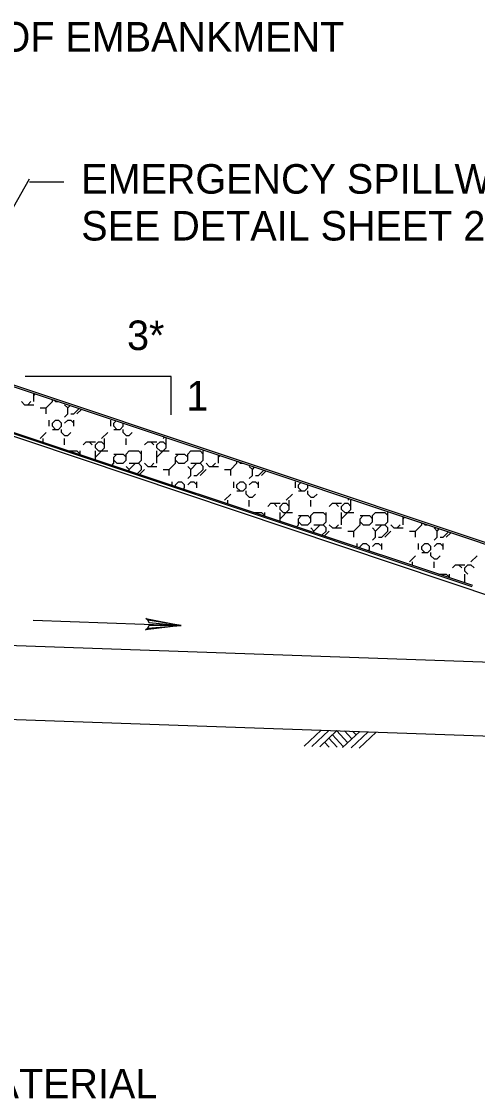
# Model space of a CAD drawing. Extents: x 636462 to 639890, y 299944 to 300538.
# Drawn here: x 638498.9 to 638545.1, y 300084.3 to 300193.5 of the extents above; entities that cross this region are included whole.
import ezdxf

# ---------------------------------------------------------------- set-up
doc = ezdxf.new("R2010")
doc.units = 0
doc.layers.add('Default', color=7, linetype='Continuous')

msp = doc.modelspace()

# ---------------------------------------------------------------- linework, layer by layer
at = {"layer": 'Default'}
for p, q in [((638489.42, 300159.53), (638499.66, 300177.55)), ((638503.16, 300177.22), (638499.66, 300177.22)), ((638465.99, 300167.34), (638586.56, 300127.15)), ((638500.1, 300154.96), (638500.1, 300155.8)), ((638499.16, 300154.65), (638498.85, 300154.96)), ((638499.48, 300154.65), (638499.79, 300154.96)), ((638500.1, 300155.58), (638500.26, 300155.75)), ((638501.35, 300154.33), (638501.98, 300154.96)), ((638501.98, 300154.96), (638501.98, 300155.17)), ((638502.29, 300154.96), (638502.12, 300155.12)), ((638502.29, 300154.96), (638502.61, 300154.96)), ((638499.16, 300154.65), (638500.1, 300154.65)), ((638500.73, 300154.33), (638501.35, 300154.33)), ((638501.35, 300153.71), (638501.35, 300154.33)), ((638503.54, 300154.33), (638503.22, 300154.65)), ((638503.22, 300153.4), (638503.54, 300153.71)), ((638503.54, 300154.33), (638503.77, 300154.57)), ((638503.54, 300153.71), (638503.54, 300154.33)), ((638503.85, 300153.71), (638504.16, 300153.71)), ((638504.16, 300153.71), (638504.71, 300154.26)), ((638504.47, 300153.71), (638504.94, 300154.18)), ((638501.66, 300152.46), (638501.66, 300153.09)), ((638501.98, 300152.77), (638502.29, 300153.09)), ((638501.98, 300152.46), (638501.98, 300152.77)), ((638502.29, 300153.09), (638502.6, 300153.09)), ((638502.91, 300152.77), (638502.6, 300153.09)), ((638502.91, 300152.46), (638502.91, 300152.77)), ((638503.22, 300152.77), (638503.54, 300153.09)), ((638503.54, 300153.09), (638503.85, 300153.09)), ((638504.16, 300152.77), (638503.85, 300153.09)), ((638504.16, 300152.46), (638504.16, 300153.09)), ((638507.91, 300152.46), (638507.91, 300153.09)), ((638508.22, 300152.77), (638508.46, 300153.01)), ((638508.22, 300152.46), (638508.22, 300152.77)), ((638509.16, 300152.77), (638509.16, 300152.77)), ((638509.16, 300152.46), (638509.16, 300152.77)), ((638500.73, 300151.21), (638501.35, 300151.84)), ((638502.29, 300152.15), (638501.98, 300152.46)), ((638501.98, 300152.15), (638502.6, 300152.15)), ((638502.6, 300152.15), (638502.91, 300152.46)), ((638502.91, 300151.84), (638502.91, 300152.15)), ((638503.22, 300151.52), (638502.91, 300151.84)), ((638503.22, 300151.52), (638503.54, 300151.52)), ((638503.54, 300151.52), (638503.85, 300151.84)), ((638506.97, 300151.21), (638507.6, 300151.84)), ((638508.53, 300152.15), (638508.22, 300152.46)), ((638508.22, 300152.15), (638508.85, 300152.15)), ((638508.85, 300152.15), (638509.16, 300152.46)), ((638509.16, 300151.84), (638509.16, 300152.15)), ((638509.47, 300151.52), (638509.16, 300151.84)), ((638509.47, 300151.52), (638509.78, 300151.52)), ((638509.78, 300151.52), (638510.09, 300151.84)), ((638501.04, 300150.8), (638501.04, 300151.21)), ((638503.22, 300150.59), (638503.22, 300151.21)), ((638505.1, 300150.59), (638505.41, 300150.9)), ((638505.41, 300150.9), (638506.35, 300150.9)), ((638506.03, 300150.59), (638505.72, 300150.9)), ((638506.35, 300150.59), (638506.66, 300150.9)), ((638506.35, 300150.28), (638506.35, 300150.59)), ((638506.66, 300150.9), (638506.97, 300150.9)), ((638507.28, 300150.59), (638506.97, 300150.9)), ((638507.28, 300150.28), (638507.28, 300151.21)), ((638509.47, 300150.59), (638509.47, 300151.21)), ((638511.34, 300150.59), (638511.66, 300150.9)), ((638511.66, 300150.9), (638512.59, 300150.9)), ((638512.28, 300150.59), (638511.97, 300150.9)), ((638512.59, 300150.59), (638512.91, 300150.9)), ((638512.59, 300150.28), (638512.59, 300150.59)), ((638512.91, 300150.9), (638513.22, 300150.9)), ((638513.22, 300151.21), (638513.37, 300151.37)), ((638513.53, 300150.59), (638513.22, 300150.9)), ((638513.53, 300150.28), (638513.53, 300151.21)), ((638503.56, 300149.96), (638504.47, 300149.96)), ((638504.79, 300149.65), (638504.47, 300149.96)), ((638504.79, 300149.56), (638504.79, 300149.96)), ((638506.66, 300149.96), (638506.35, 300150.28)), ((638506.35, 300149.34), (638507.28, 300150.28)), ((638506.35, 300149.04), (638506.35, 300149.96)), ((638506.66, 300149.96), (638507.6, 300149.96)), ((638508.22, 300149.34), (638508.53, 300149.65)), ((638508.22, 300149.65), (638509.16, 300149.65)), ((638508.22, 300148.71), (638508.22, 300149.34)), ((638509.47, 300149.34), (638509.16, 300149.65)), ((638509.47, 300149.65), (638509.78, 300149.96)), ((638509.47, 300149.03), (638509.47, 300149.65)), ((638509.78, 300149.96), (638510.72, 300149.96)), ((638511.03, 300149.65), (638510.72, 300149.96)), ((638511.03, 300149.03), (638511.03, 300149.96)), ((638512.91, 300149.96), (638512.59, 300150.28)), ((638512.59, 300149.34), (638513.53, 300150.28)), ((638512.59, 300148.71), (638512.59, 300149.96)), ((638512.91, 300149.96), (638513.84, 300149.96)), ((638514.47, 300149.34), (638514.78, 300149.65)), ((638514.47, 300149.65), (638515.4, 300149.65)), ((638514.47, 300148.71), (638514.47, 300149.34)), ((638515.72, 300149.34), (638515.4, 300149.65)), ((638515.72, 300149.65), (638516.03, 300149.96)), ((638515.72, 300149.03), (638515.72, 300149.65)), ((638516.03, 300149.96), (638516.97, 300149.96)), ((638517.28, 300149.65), (638516.97, 300149.96)), ((638517.28, 300149.03), (638517.28, 300149.96)), ((638518.84, 300148.71), (638518.84, 300149.54)), ((638518.84, 300149.34), (638518.99, 300149.49)), ((638508, 300148.49), (638508.22, 300148.71)), ((638508.53, 300148.71), (638508.22, 300149.03)), ((638508.53, 300148.71), (638509.16, 300148.71)), ((638509.16, 300148.71), (638509.47, 300149.03)), ((638509.78, 300148.09), (638509.47, 300148.4)), ((638509.78, 300148.09), (638510.41, 300148.71)), ((638509.78, 300148.71), (638510.72, 300148.71)), ((638510.72, 300148.71), (638511.03, 300149.03)), ((638511.03, 300148.4), (638510.72, 300148.71)), ((638511.03, 300148.09), (638511.03, 300148.4)), ((638511.66, 300148.4), (638511.34, 300148.71)), ((638511.66, 300148.4), (638512.59, 300148.4)), ((638511.97, 300148.4), (638512.28, 300148.71)), ((638513.84, 300148.09), (638514.47, 300148.71)), ((638514.78, 300148.71), (638514.47, 300149.03)), ((638514.78, 300148.71), (638515.4, 300148.71)), ((638515.4, 300148.71), (638515.72, 300149.03)), ((638516.03, 300148.09), (638515.72, 300148.4)), ((638516.03, 300148.09), (638516.65, 300148.71)), ((638516.03, 300148.71), (638516.97, 300148.71)), ((638516.97, 300148.71), (638517.28, 300149.03)), ((638517.28, 300148.4), (638516.97, 300148.71)), ((638517.28, 300148.09), (638517.28, 300148.4)), ((638517.9, 300148.4), (638517.59, 300148.71)), ((638517.9, 300148.4), (638518.84, 300148.4)), ((638518.21, 300148.4), (638518.53, 300148.71)), ((638520.09, 300148.09), (638520.71, 300148.71)), ((638520.71, 300148.71), (638520.71, 300148.92)), ((638521.03, 300148.71), (638520.88, 300148.86)), ((638521.03, 300148.71), (638521.32, 300148.71)), ((638522.27, 300148.09), (638521.96, 300148.4)), ((638522.27, 300148.09), (638522.5, 300148.32)), ((638509.78, 300147.9), (638509.78, 300148.09)), ((638510.58, 300147.63), (638511.03, 300148.09)), ((638510.81, 300147.56), (638511.34, 300148.09)), ((638513.22, 300148.09), (638513.84, 300148.09)), ((638513.84, 300147.46), (638513.84, 300148.09)), ((638515.72, 300147.15), (638516.03, 300147.46)), ((638516.03, 300147.46), (638516.03, 300148.09)), ((638516.34, 300147.46), (638516.65, 300147.46)), ((638516.65, 300147.46), (638517.28, 300148.09)), ((638516.97, 300147.46), (638517.59, 300148.09)), ((638519.46, 300148.09), (638520.09, 300148.09)), ((638520.09, 300147.46), (638520.09, 300148.09)), ((638521.96, 300147.15), (638522.27, 300147.46)), ((638522.27, 300147.46), (638522.27, 300148.09)), ((638522.59, 300147.46), (638522.9, 300147.46)), ((638522.9, 300147.46), (638523.44, 300148.01)), ((638523.21, 300147.46), (638523.67, 300147.93)), ((638514.15, 300146.45), (638514.15, 300146.84)), ((638514.47, 300146.53), (638514.78, 300146.84)), ((638514.47, 300146.34), (638514.47, 300146.53)), ((638514.78, 300146.84), (638515.09, 300146.84)), ((638515.4, 300146.53), (638515.09, 300146.84)), ((638515.27, 300146.08), (638515.4, 300146.22)), ((638515.4, 300146.22), (638515.4, 300146.53)), ((638515.72, 300146.53), (638516.03, 300146.84)), ((638516.03, 300146.84), (638516.34, 300146.84)), ((638516.65, 300146.53), (638516.34, 300146.84)), ((638516.65, 300146.22), (638516.65, 300146.84)), ((638520.4, 300146.22), (638520.4, 300146.84)), ((638520.71, 300146.53), (638521.03, 300146.84)), ((638520.71, 300146.22), (638520.71, 300146.53)), ((638521.03, 300145.9), (638520.71, 300146.22)), ((638521.03, 300146.84), (638521.34, 300146.84)), ((638521.65, 300146.53), (638521.34, 300146.84)), ((638521.34, 300145.9), (638521.65, 300146.22)), ((638521.65, 300146.22), (638521.65, 300146.53)), ((638521.96, 300146.53), (638522.27, 300146.84)), ((638522.27, 300146.84), (638522.59, 300146.84)), ((638522.9, 300146.53), (638522.59, 300146.84)), ((638522.9, 300146.22), (638522.9, 300146.84)), ((638526.65, 300146.22), (638526.65, 300146.84)), ((638526.96, 300146.53), (638527.19, 300146.75)), ((638526.96, 300146.22), (638526.96, 300146.53)), ((638527.27, 300145.9), (638526.96, 300146.22)), ((638527.58, 300145.9), (638527.9, 300146.22)), ((638527.9, 300146.22), (638527.9, 300146.52)), ((638519.46, 300144.97), (638520.09, 300145.59)), ((638519.78, 300144.58), (638519.78, 300144.97)), ((638520.71, 300145.9), (638521.34, 300145.9)), ((638521.65, 300145.59), (638521.65, 300145.9)), ((638521.96, 300145.28), (638521.65, 300145.59)), ((638521.96, 300145.28), (638522.27, 300145.28)), ((638521.96, 300144.34), (638521.96, 300144.97)), ((638522.27, 300145.28), (638522.59, 300145.59)), ((638525.71, 300144.97), (638526.33, 300145.59)), ((638526.02, 300144.03), (638526.02, 300144.97)), ((638526.96, 300145.9), (638527.58, 300145.9)), ((638527.9, 300145.59), (638527.9, 300145.9)), ((638528.21, 300145.28), (638527.9, 300145.59)), ((638528.21, 300145.28), (638528.52, 300145.28)), ((638528.21, 300144.34), (638528.21, 300144.97)), ((638528.52, 300145.28), (638528.83, 300145.59)), ((638531.96, 300144.97), (638532.1, 300145.11)), ((638532.27, 300144.03), (638532.27, 300144.97)), ((638523.84, 300144.34), (638524.15, 300144.65)), ((638524.15, 300144.65), (638525.09, 300144.65)), ((638524.77, 300144.34), (638524.46, 300144.65)), ((638525.09, 300144.34), (638525.4, 300144.65)), ((638525.09, 300144.03), (638525.09, 300144.34)), ((638525.4, 300143.72), (638525.09, 300144.03)), ((638525.09, 300143.09), (638526.02, 300144.03)), ((638525.4, 300144.65), (638525.71, 300144.65)), ((638526.02, 300144.34), (638525.71, 300144.65)), ((638530.08, 300144.34), (638530.39, 300144.65)), ((638530.39, 300144.65), (638531.33, 300144.65)), ((638531.02, 300144.34), (638530.71, 300144.65)), ((638531.33, 300144.34), (638531.64, 300144.65)), ((638531.33, 300144.03), (638531.33, 300144.34)), ((638531.64, 300143.72), (638531.33, 300144.03)), ((638531.33, 300143.09), (638532.27, 300144.03)), ((638531.64, 300144.65), (638531.96, 300144.65)), ((638532.27, 300144.34), (638531.96, 300144.65)), ((638522.38, 300143.72), (638523.21, 300143.72)), ((638523.52, 300143.4), (638523.21, 300143.72)), ((638523.52, 300143.34), (638523.52, 300143.72)), ((638525.09, 300142.82), (638525.09, 300143.72)), ((638525.4, 300143.72), (638526.33, 300143.72)), ((638526.96, 300143.09), (638527.27, 300143.4)), ((638526.96, 300143.4), (638527.9, 300143.4)), ((638526.96, 300142.47), (638526.96, 300143.09)), ((638527.27, 300142.47), (638526.96, 300142.78)), ((638528.21, 300143.09), (638527.9, 300143.4)), ((638527.9, 300142.47), (638528.21, 300142.78)), ((638528.21, 300143.4), (638528.52, 300143.72)), ((638528.21, 300142.78), (638528.21, 300143.4)), ((638528.52, 300143.72), (638529.46, 300143.72)), ((638529.77, 300143.4), (638529.46, 300143.72)), ((638529.46, 300142.47), (638529.77, 300142.78)), ((638529.77, 300142.78), (638529.77, 300143.72)), ((638531.33, 300142.47), (638531.33, 300143.72)), ((638531.64, 300143.72), (638532.58, 300143.72)), ((638533.2, 300143.09), (638533.52, 300143.4)), ((638533.2, 300143.4), (638534.14, 300143.4)), ((638533.2, 300142.47), (638533.2, 300143.09)), ((638533.52, 300142.47), (638533.2, 300142.78)), ((638534.45, 300143.09), (638534.14, 300143.4)), ((638534.14, 300142.47), (638534.45, 300142.78)), ((638534.45, 300143.4), (638534.77, 300143.72)), ((638534.45, 300142.78), (638534.45, 300143.4)), ((638534.77, 300143.72), (638535.7, 300143.72)), ((638536.02, 300143.4), (638535.7, 300143.72)), ((638535.7, 300142.47), (638536.02, 300142.78)), ((638536.02, 300142.78), (638536.02, 300143.72)), ((638537.58, 300142.47), (638537.58, 300143.28)), ((638537.58, 300143.09), (638537.72, 300143.24)), ((638526.75, 300142.26), (638526.96, 300142.47)), ((638527.27, 300142.47), (638527.9, 300142.47)), ((638528.52, 300141.84), (638528.21, 300142.16)), ((638528.52, 300141.84), (638529.14, 300142.47)), ((638528.52, 300142.47), (638529.46, 300142.47)), ((638528.52, 300141.68), (638528.52, 300141.84)), ((638529.33, 300141.41), (638529.77, 300141.84)), ((638529.77, 300142.16), (638529.46, 300142.47)), ((638529.57, 300141.33), (638530.08, 300141.84)), ((638529.77, 300141.84), (638529.77, 300142.16)), ((638530.39, 300142.16), (638530.08, 300142.47)), ((638530.39, 300142.16), (638531.33, 300142.16)), ((638530.71, 300142.16), (638531.02, 300142.47)), ((638531.96, 300141.84), (638532.58, 300141.84)), ((638532.58, 300141.84), (638533.2, 300142.47)), ((638532.58, 300141.22), (638532.58, 300141.84)), ((638533.52, 300142.47), (638534.14, 300142.47)), ((638534.77, 300141.84), (638534.45, 300142.16)), ((638534.77, 300141.84), (638535.39, 300142.47)), ((638534.77, 300142.47), (638535.7, 300142.47)), ((638534.77, 300141.22), (638534.77, 300141.84)), ((638535.39, 300141.22), (638536.02, 300141.84)), ((638536.02, 300142.16), (638535.7, 300142.47)), ((638535.7, 300141.22), (638536.33, 300141.84)), ((638536.02, 300141.84), (638536.02, 300142.16)), ((638536.64, 300142.16), (638536.33, 300142.47)), ((638536.64, 300142.16), (638537.58, 300142.16)), ((638536.95, 300142.16), (638537.26, 300142.47)), ((638538.2, 300141.84), (638538.83, 300141.84)), ((638538.83, 300141.84), (638539.45, 300142.47)), ((638538.83, 300141.22), (638538.83, 300141.84)), ((638539.45, 300142.47), (638539.45, 300142.66)), ((638539.76, 300142.47), (638539.63, 300142.6)), ((638539.76, 300142.47), (638540.02, 300142.47)), ((638541.01, 300141.84), (638540.7, 300142.16)), ((638541.01, 300141.84), (638541.23, 300142.06)), ((638541.01, 300141.22), (638541.01, 300141.84)), ((638541.64, 300141.22), (638542.17, 300141.75)), ((638541.95, 300141.22), (638542.4, 300141.67)), ((638532.89, 300140.23), (638532.89, 300140.59)), ((638533.2, 300140.28), (638533.52, 300140.59)), ((638533.52, 300140.59), (638533.83, 300140.59)), ((638534.14, 300140.28), (638533.83, 300140.59)), ((638534.45, 300140.91), (638534.77, 300141.22)), ((638534.45, 300140.28), (638534.77, 300140.59)), ((638534.77, 300140.59), (638535.08, 300140.59)), ((638535.08, 300141.22), (638535.39, 300141.22)), ((638535.39, 300140.28), (638535.08, 300140.59)), ((638535.39, 300139.97), (638535.39, 300140.59)), ((638539.14, 300139.97), (638539.14, 300140.59)), ((638539.45, 300140.28), (638539.76, 300140.59)), ((638539.76, 300140.59), (638540.08, 300140.59)), ((638540.39, 300140.28), (638540.08, 300140.59)), ((638540.7, 300140.91), (638541.01, 300141.22)), ((638540.7, 300140.28), (638541.01, 300140.59)), ((638541.01, 300140.59), (638541.32, 300140.59)), ((638541.32, 300141.22), (638541.64, 300141.22)), ((638541.64, 300140.28), (638541.32, 300140.59)), ((638541.64, 300139.97), (638541.64, 300140.59)), ((638533.2, 300140.12), (638533.2, 300140.28)), ((638534.02, 300139.85), (638534.14, 300139.97)), ((638534.14, 300139.97), (638534.14, 300140.28)), ((638539.45, 300139.97), (638539.45, 300140.28)), ((638539.76, 300139.66), (638539.45, 300139.97)), ((638539.45, 300139.66), (638540.08, 300139.66)), ((638540.08, 300139.66), (638540.39, 300139.97)), ((638540.39, 300139.97), (638540.39, 300140.28)), ((638540.39, 300139.34), (638540.39, 300139.66)), ((638538.2, 300138.72), (638538.83, 300139.34)), ((638538.51, 300138.36), (638538.51, 300138.72)), ((638540.7, 300139.03), (638540.39, 300139.34)), ((638540.7, 300139.03), (638541.01, 300139.03)), ((638540.7, 300138.1), (638540.7, 300138.72)), ((638541.01, 300139.03), (638541.32, 300139.34)), ((638542.57, 300138.1), (638542.89, 300138.41)), ((638542.89, 300138.41), (638543.82, 300138.41)), ((638543.51, 300138.1), (638543.2, 300138.41)), ((638543.82, 300138.1), (638544.14, 300138.41)), ((638544.14, 300138.41), (638544.45, 300138.41)), ((638544.45, 300138.72), (638545.07, 300139.34)), ((638544.76, 300138.1), (638544.45, 300138.41)), ((638541.19, 300137.47), (638541.95, 300137.47)), ((638542.26, 300137.16), (638541.95, 300137.47)), ((638542.26, 300137.12), (638542.26, 300137.47)), ((638543.82, 300137.78), (638543.82, 300138.1)), ((638544.14, 300137.47), (638543.82, 300137.78)), ((638543.82, 300136.6), (638543.82, 300137.47)), ((638500.04, 300132.79), (638515.04, 300132.27)), ((638480.85, 300130.84), (638592.67, 300126.94)), ((638480.59, 300123.35), (638592.41, 300119.45)), ((638527.51, 300120.03), (638529.24, 300121.64)), ((638528.3, 300120), (638530.04, 300121.62)), ((638529.11, 300119.97), (638530.84, 300121.6)), ((638530.39, 300121.17), (638531.51, 300119.97)), ((638530.81, 300121.6), (638531.95, 300120.37)), ((638531.43, 300119.89), (638533.18, 300121.52)), ((638531.62, 300121.57), (638532.36, 300120.77)), ((638532.29, 300119.86), (638534.01, 300121.47)), ((638532.43, 300121.54), (638532.79, 300121.16)), ((638533.1, 300119.83), (638534.82, 300121.44)), ((638529.6, 300120.43), (638530.08, 300119.91)), ((638530.02, 300120.82), (638530.87, 300119.91))]:
    msp.add_line(p, q, dxfattribs=at)
for points in [[(638419.79, 300159.33), (638427.93, 300154.6), (638488.62, 300154.6), (638568.6, 300127.8)], [(638544.63, 300136.33), (638488.7, 300154.9), (638428.03, 300154.92), (638420.2, 300159.48), (638489.37, 300159.38), (638585.28, 300127.35), (638570.05, 300127.89), (638546.38, 300135.75)], [(638514.02, 300153.61), (638514.02, 300157.5), (638499.23, 300157.5)], [(638427.98, 300154.85), (638444.76, 300154.85), (638488.66, 300154.85), (638544.53, 300136.22)], [(638511.65, 300132.81), (638511.77, 300132.56), (638515.04, 300132.27), (638511.65, 300132.81), (638511.48, 300132.97), (638515.04, 300132.27), (638511.76, 300132.22), (638511.63, 300131.98), (638515.04, 300132.27), (638511.44, 300131.82), (638511.63, 300131.98)]]:
    msp.add_lwpolyline(points, dxfattribs=at)

# ---------------------------------------------------------------- texts
for s, height, p in [('TOP OF EMBANKMENT ', 2.998, (638487.27, 300190.46)), ('EMERGENCY SPILLWAY,', 2.998, (638504.91, 300176.05)), ('SEE DETAIL SHEET 2', 2.998, (638504.91, 300171.3)), ('3*', 2.998, (638509.56, 300160.19)), ('1', 3, (638515.58, 300154.06)), ('EMBANKMENT MATERIAL', 2.998, (638463.18, 300084.3))]:
    msp.add_text(s, height=height, dxfattribs=at).set_placement(p)

doc.saveas('drawing.dxf')
